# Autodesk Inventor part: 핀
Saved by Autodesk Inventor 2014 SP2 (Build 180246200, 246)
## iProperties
Created: 2025-07
Part Number: 핀
Material: Generic
Document SubType Name: Modeling
Designer: Administrator
Density: 1 g/cm^3
Appearance: Default
Author: Administrator
Author: jhkim
Creation Date: 2025-06-11
Sending System: Autodesk Inventor 2026
Preprocessor: ST-DEVELOPER v20.1
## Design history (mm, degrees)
node "핀1"
node "솔리드1"
node "기준1"
